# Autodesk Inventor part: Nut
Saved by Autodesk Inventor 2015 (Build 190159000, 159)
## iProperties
Created: 2015-04
Part Number: Nut
Material: Generic
Document SubType Name: Modeling
Designer: Gabriel Cabellos
Density: 1 g/cm^3
Appearance: Default
Author: Gabriel Cabellos
Sending System: SolidWorks 2011
Last Author: Pets
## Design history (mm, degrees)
node "Nut.ipt1"
node "Chamfer1"
node "Base1"
